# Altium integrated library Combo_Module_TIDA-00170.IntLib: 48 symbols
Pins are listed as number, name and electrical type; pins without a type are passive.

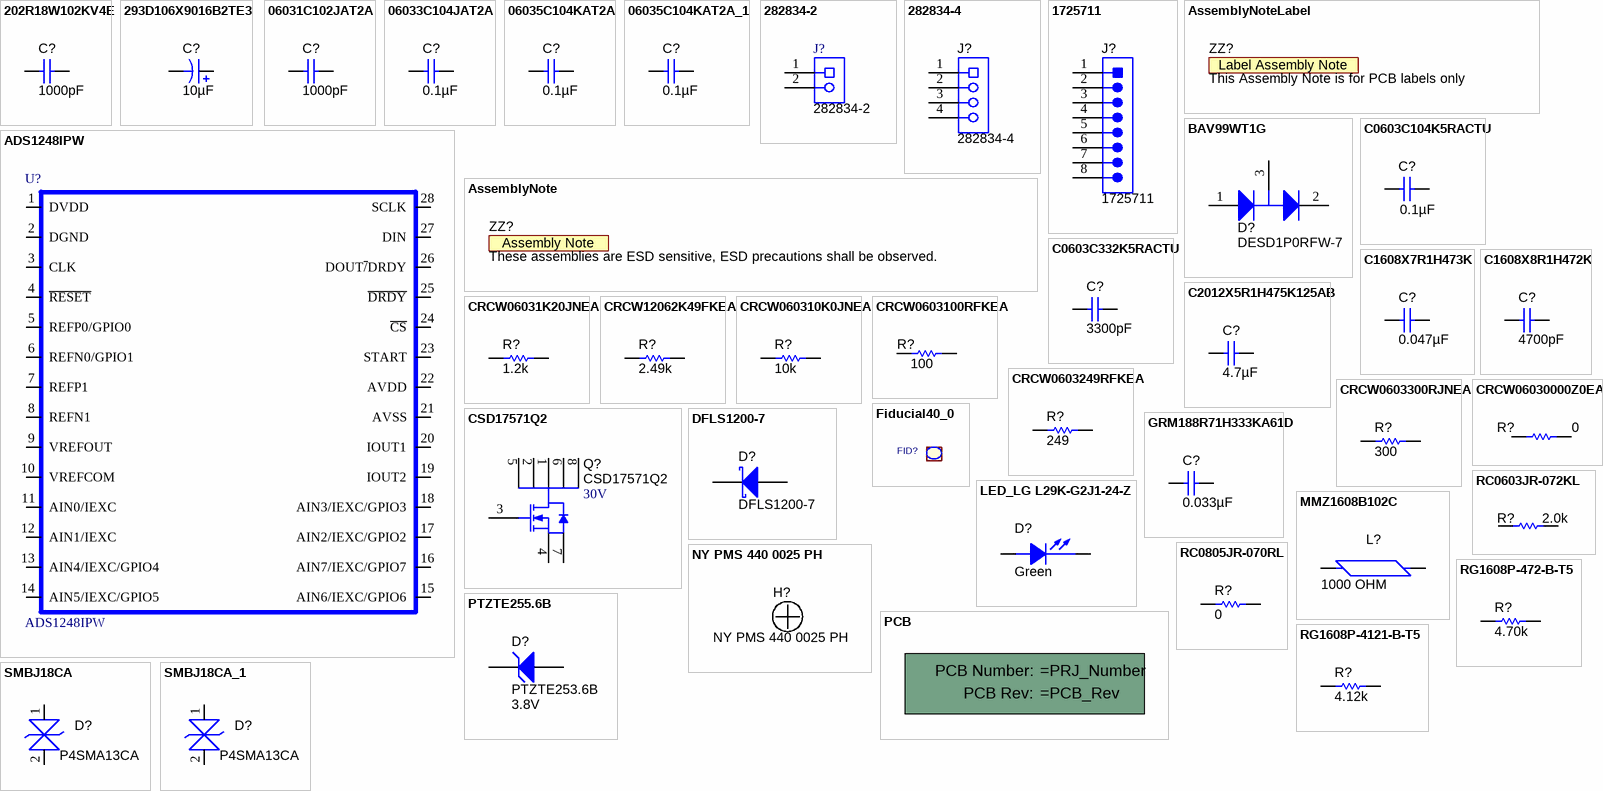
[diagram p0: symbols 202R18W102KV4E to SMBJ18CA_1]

## 202R18W102KV4E
designator C?, comment value 1000pF  (hidden comment: CC1206KRX7R0BB102)
CAP CER 1000PF 100V 10% X7R 1206; Manufacturer: Yageo; Polarized: N; CompType: Capacitor; Cap_F: 0.000000001; Tolerance_%: 0; Value2: 2KV; Cap_Case: 1206
signal-integrity model Cap
simulation model Cap
footprint 1206
footprint 1206M
footprint 1206L
pins: 1, 2

## 293D106X9016B2TE3
designator C?  ValueDisplayed: 10µF  (hidden comment: 293D106X9016B2TE3)
CAP, TA, 10 µF, 16 V, +/- 10%, 2 ohm, SMD; Manufacturer: Vishay-Sprague; Polarized: Y; CompType: Capacitor; Value: 10uF; U/M: EA; Cap_F: 0.00001; Tolerance_%: 10; Value1: 2 ohm; VDC_V: 16; Value2: 16V; ESR_ohm: 2; IRMS_A: 0.21; TaMin_C: -55; TaMax_C: 125; Cap_Case: B
signal-integrity model Cap
simulation model Cap
footprint 3528-21
pins: 1 +, 2 -

## 06031C102JAT2A
designator C?  ValueDisplayed: 1000pF  (hidden comment: 06031C102JAT2A)
CAP, CERM, 1000pF, 100V, +/-5%, X7R, 0603; Manufacturer: AVX; Polarized: N; CompType: Capacitor; U/M: EA; Cap_F: 0.000000001; Tolerance_%: 5; ESR_Ohm: 0.276; Value1: 0.276 ohm; VDC_V: 100; TaMin_C: -55; TaMax_C: 125; Cap_Case: 0603
signal-integrity model Cap
simulation model Cap
footprint 0603 (0603 from SM-752 data)
footprint 0603M
footprint 0603L
footprint 0603_HV
pins: 1, 2

## 06033C104JAT2A
designator C?  ValueDisplayed: 0.1µF  (hidden comment: 06033C104JAT2A)
CAP, CERM, 0.1uF, 25V, +/-5%, X7R, 0603; Manufacturer: AVX; Polarized: N; CompType: Capacitor; U/M: EA; Cap_F: 0.0000001; Tolerance_%: 5; ESR_Ohm: 0.05; Value1: 0.05 ohm; VDC_V: 25; TaMin_C: -55; TaMax_C: 125; Cap_Case: 0603
signal-integrity model Cap
simulation model Cap
footprint 0603 (0603 from SM-752 data)
footprint 0603M
footprint 0603L
footprint 0603_HV
pins: 1, 2

## 06035C104KAT2A
designator C?  ValueDisplayed: 0.1µF  (hidden comment: 06035C104KAT2A)
CAP, CERM, 0.1uF, 50V, +/-10%, X7R, 0603; Manufacturer: AVX; Polarized: N; CompType: Capacitor; U/M: EA; Cap_F: 0.0000001; Tolerance_%: 10; Value1: Unknown; VDC_V: 50; TaMin_C: -55; TaMax_C: 125; Cap_Case: 0603
signal-integrity model Cap
simulation model Cap
footprint 0603
footprint 0603M
footprint 0603L
footprint 0603_HV
footprint 0603S
pins: 1, 2

## 06035C104KAT2A_1
designator C?, comment ValueDisplayed: 0.1µF  (hidden comment: 06035C104KAT2A)
CAP, CERM, 0.1uF, 50V, +/-10%, X7R, 0603; Manufacturer: AVX; Polarized: N; CompType: Capacitor; U/M: EA; Cap_F: 0.0000001; Tolerance_%: 10; Value1: Unknown; VDC_V: 50; TaMin_C: -55; TaMax_C: 125; Cap_Case: 0603
signal-integrity model Cap
simulation model Cap
footprint 0603
footprint 0603M
footprint 0603L
footprint 0603_HV
pins: 1, 2

## 282834-2
designator J?
Terminal Block, 2x1, 2.54mm, TH; Manufacturer: TE Connectivity; SymbolCreator: a0412235; U/M: EA
footprint TEC_282834-2
pins: 1, 2

## 282834-4
designator J?
Receptacle, 100mil, 4X1 TH; Manufacturer: TE Connectivity; SymbolCreator: a0411947; U/M: EA
footprint TEC_282834-4
pins: 1, 2, 3, 4

## 1725711
designator J?
Terminal Block, 8x1, 2.54 mm, TH; Manufacturer: Phoenix Contact; SymbolCreator: a0411947; U/M: EA
footprint CONN_1725711
pins: 1, 2, 3, 4, 5, 6, 7, 8

## ADS1248IPW
designator U?
IC, 24-Bit A-D Converters for Temperature Sensors; Manufacturer: TI; Alternate Manufacturer: None; Area: 164.280
footprint PW28
pins: 1 DVDD, 2 DGND, 3 CLK, 4 ~{RESET}, 5 REFP0/GPIO0, 6 REFN0/GPIO1, 7 REFP1, 8 REFN1, 9 VREFOUT, 10 VREFCOM, 11 AIN0/IEXC, 12 AIN1/IEXC, 13 AIN4/IEXC/GPIO4, 14 AIN5/IEXC/GPIO5, 15 AIN6/IEXC/GPIO6, 16 AIN7/IEXC/GPIO7, 17 AIN2/IEXC/GPIO2, 18 AIN3/IEXC/GPIO3, 19 IOUT2, 20 IOUT1, 21 AVSS, 22 AVDD, 23 START, 24 ~{CS}, 25 ~{DRDY}, 26 DOUT~{/}DRDY, 27 DIN, 28 SCLK

## AssemblyNote
designator ZZ?, comment These assemblies are ESD sensitive, ESD precautions shall be observed.  (no BOM)
SymbolCreator: codlsc; CompType: AssemblyNote
footprint AssemblyNote

## AssemblyNoteLabel
designator ZZ?, comment This Assembly Note is for PCB labels only  (no BOM)
SymbolCreator: a0412235
footprint AssemblyNoteLabel

## BAV99WT1G
designator D?, comment DESD1P0RFW-7
Diode, P-N, 70V, 0.2A, SOT-323; Manufacturer: Diodes Inc; Value: DNP
footprint SOT-323
pins: 1 A, 2 K, 3 C
1 alternate drawing of the same symbol

## C0603C104K5RACTU
designator C?  ValueDisplayed: 0.1µF  (hidden comment: C0603C104K5RACTU)
CAP, CERM, 0.1uF, 50V, +/-10%, X7R, 0603; Manufacturer: Kemet; Polarized: N; CompType: Capacitor; U/M: EA; Cap_F: 0.0000001; Tolerance_%: 10; Value1: Unknown; VDC_V: 50; TaMin_C: -55; TaMax_C: 125; Cap_Case: 0603
signal-integrity model Cap
simulation model Cap
footprint 0603
footprint 0603M
footprint 0603L
footprint 0603_HV
footprint 0603S
pins: 1, 2

## C0603C332K5RACTU
designator C?  ValueDisplayed: 3300pF  (hidden comment: C0603C332K5RACTU)
CAP, CERM, 3300pF, 50V, +/-10%, X7R, 0603; Manufacturer: Kemet; Polarized: N; CompType: Capacitor; U/M: EA; Cap_F: 0.0000000033; Tolerance_%: 10; Value1: Unknown; VDC_V: 50; TaMin_C: -55; TaMax_C: 125; Cap_Case: 0603
signal-integrity model Cap
simulation model Cap
footprint 0603
footprint 0603M
footprint 0603L
footprint 0603_HV
footprint 0603S
pins: 1, 2

## C1608X7R1H473K
designator C?  ValueDisplayed: 0.047µF  (hidden comment: C1608X7R1H473K)
CAP, CERM, 0.047uF, 50V, +/-10%, X7R, 0603; Manufacturer: TDK; Polarized: N; CompType: Capacitor; U/M: EA; Cap_F: 0.000000047; Tolerance_%: 10; ESR_Ohm: 0.0234; Value1: 0.0234 ohm; VDC_V: 50; TaMin_C: -55; TaMax_C: 125; Cap_Case: 0603
signal-integrity model Cap
simulation model Cap
footprint 0603
footprint 0603M
footprint 0603L
footprint 0603_HV
footprint 0603S
pins: 1, 2

## C1608X8R1H472K
designator C?  ValueDisplayed: 4700pF  (hidden comment: C1608X8R1H472K)
CAP, CERM, 4700pF, 50V, +/-10%, X8R, 0603; Manufacturer: TDK; Polarized: N; CompType: Capacitor; U/M: EA; Cap_F: 0.0000000047; Tolerance_%: 10; ESR_Ohm: 0.0973; Value1: 0.0973 ohm; VDC_V: 50; TaMin_C: -55; TaMax_C: 150; Cap_Case: 0603
signal-integrity model Cap
simulation model Cap
footprint 0603
footprint 0603M
footprint 0603L
footprint 0603_HV
footprint 0603S
pins: 1, 2

## C2012X5R1H475K125AB
designator C?  ValueDisplayed: 4.7µF  (hidden comment: C2012X5R1H475K125AB)
CAP, CERM, 4.7uF, 50V, +/-10%, X5R, 0805; Manufacturer: TDK; Polarized: N; CompType: Capacitor; U/M: EA; Cap_F: 0.0000047; Tolerance_%: 10; Value1: Unknown; VDC_V: 50; TaMin_C: -55; TaMax_C: 85; Cap_Case: 0805
signal-integrity model Cap
simulation model Cap
footprint 0805_HV
footprint 0805
footprint 0805M
footprint 0805L
pins: 1, 2

## CRCW06031K20JNEA
designator R?  ValueDisplayed: 1.2k  (hidden comment: CRCW06031K20JNEA)
RES, 1.2 k, 5%, 0.1 W, 0603; Manufacturer: Vishay-Dale; CompType: Resistor; Res_ohm: 1200; Value: 1.2k; Value_Code: 1k20; Tolerance_%: 5; Power_W: 0.1; Value2: 0.1W; VDC_V: 75; TempCo: 200 ppm/C; EIA_Code: E24; U/M: EA
signal-integrity model Resistor
simulation model Resistor
footprint 0603
footprint 0603M
footprint 0603L
footprint 0603_HV
footprint 0603S
pins: 1, 2

## CRCW12062K49FKEA
designator R?, comment value 2.49k  (hidden comment: TNPW12062K49BEEA)
RES 2.49K OHM 1/4W 0.1% 1206; Manufacturer: Vishay-Dale; CompType: Resistor; Res_ohm: 2490; Value_Code: 2k49; Tolerance_%: 1; Power_W: 0.25; Value2: 0.25W; VDC_V: 200; TempCo: 100 ppm/C; EIA_Code: E96; U/M: EA
signal-integrity model Resistor
simulation model Resistor
footprint 1206
footprint 1206M
footprint 1206L
pins: 1, 2

## CRCW060310K0JNEA
designator R?  ValueDisplayed: 10k  (hidden comment: CRCW060310K0JNEA)
RES, 10 k, 5%, 0.1 W, 0603; Manufacturer: Vishay-Dale; CompType: Resistor; Res_ohm: 10000; Value: 10k; Value_Code: 10k0; Tolerance_%: 5; Power_W: 0.1; Value2: 0.1W; VDC_V: 75; TempCo: 200 ppm/C; EIA_Code: E24; U/M: EA
signal-integrity model Resistor
simulation model Resistor
footprint 0603
footprint 0603M
footprint 0603L
footprint 0603_HV
footprint 0603S
pins: 1, 2

## CRCW0603100RFKEA
designator R?  ValueDisplayed: 100  (hidden comment: CRCW0603100RFKEA)
RES, 100, 1%, 0.1 W, 0603; Manufacturer: Vishay-Dale; CompType: Resistor; Value: 100; Value_Code: 100R; Tolerance_%: 1; Power_W: 0.1; Value2: 0.1W; VDC_V: 75; TempCo: 100 ppm/C; EIA_Code: E96; U/M: EA
signal-integrity model Resistor
simulation model Resistor
footprint 0603
footprint 0603M
footprint 0603L
footprint 0603_HV
footprint 0603S
pins: 1, 2

## CRCW0603249RFKEA
designator R?  ValueDisplayed: 249  (hidden comment: CRCW0603249RFKEA)
RES, 249, 1%, 0.1 W, 0603; Manufacturer: Vishay-Dale; CompType: Resistor; Value: 249; Value_Code: 249R; Tolerance_%: 1; Power_W: 0.1; Value2: 0.1W; VDC_V: 75; TempCo: 100 ppm/C; EIA_Code: E96; U/M: EA
signal-integrity model Resistor
simulation model Resistor
footprint 0603
footprint 0603M
footprint 0603L
footprint 0603_HV
footprint 0603S
pins: 1, 2

## CRCW0603300RJNEA
designator R?  value 300  (hidden comment: CRCW0603300RJNEA)
RES, 300 ohm, 5%, 0.1W, 0603; Manufacturer: Vishay-Dale; CompType: Resistor; Value_Code: 300R; Tolerance_%: 5; Power_W: 0.1; VDC_V: 75; TempCo: 200 ppm/C; EIA_Code: E24; U/M: EA
signal-integrity model Resistor
simulation model Resistor
footprint 0603 (0603 from SM-752 data)
footprint 0603M
footprint 0603L
footprint 0603_HV
footprint 0603
footprint 0603_HV
footprint 0603L
footprint 0603M
simulation model Resistor
signal-integrity model Resistor
pins: 1, 2

## CRCW06030000Z0EA
designator R?  ValueDisplayed: 0  (hidden comment: CRCW06030000Z0EA)
RES, 0, 5%, 0.1 W, 0603; Manufacturer: Vishay-Dale; CompType: Resistor; Value: 0; Value_Code: 0000; Tolerance_%: 5; Power_W: 0.1; Value2: 0.1W; VDC_V: 75; TempCo: 200 ppm/C; EIA_Code: E24; U/M: EA
signal-integrity model Resistor
simulation model Resistor
footprint 0603
footprint 0603M
footprint 0603L
footprint 0603_HV
footprint 0603S
pins: 1, 2

## CSD17571Q2
designator Q?  value 30V
MOSFET, N-CH, 30V, 22A, SON 2X2 MM; Manufacturer: TEXAS INSTRUMENTS; CompType: POWER MOSFET
footprint SON_CSD17571Q2 (Footprint not found)
pins: 1 D, 2 D, 3 G, 4 S, 5 D, 6 D, 7 S, 8 D

## DFLS1200-7
designator D?
Diode, Schottky, 200V, 1A, PowerDI123; Manufacturer: Diodes Inc.; U/M: EA; Vf_V: 0.85; Value2: 0.85V; Io_A: 1; Vr_V: 200; TJmax_C: 175; RJC_CperW: 7
signal-integrity model Diode
simulation model DI_DFLS1200
footprint powerDI123
pins: 1 K, 2 A

## Fiducial40_0
designator FID?, comment Fiducial40_80  (value not drawn)
footprint FID_TOP_40_80
footprint FID_TOP_40_80
footprint FID_TOP_40_80BA
pins: 1

## GRM188R71H333KA61D
designator C?  ValueDisplayed: 0.033µF  (hidden comment: GRM188R71H333KA61D)
CAP, CERM, 0.033uF, 50V, +/-10%, X7R, 0603; Manufacturer: MuRata; Polarized: N; CompType: Capacitor; U/M: EA; Cap_F: 0.000000033; Tolerance_%: 10; Value1: Unknown; VDC_V: 50; TaMin_C: -55; TaMax_C: 125; Cap_Case: 0603
signal-integrity model Cap
simulation model Cap
footprint 0603
footprint 0603M
footprint 0603L
footprint 0603_HV
footprint 0603S
pins: 1, 2

## LED_LG L29K-G2J1-24-Z
designator D?  value Green  (hidden comment: LED_LG L29K-G2J1-24-Z)
LED SmartLED Green 570NM; Manufacturer: OSRAM; SymbolCreator: x0120606
footprint LED0603AA
pins: 1 C, 2 A

## MMZ1608B102C
designator L?, comment 1000 OHM
FERRITE CHIP 1000 OHM 300MA 0603; PartNumber: MMZ1608B102C; Manufacturer: TDK Corporation; CompType: Ferrite Bead
footprint FB0603
pins: 1, 2

## NY PMS 440 0025 PH
designator H?
Machine Screw, Round, #4-40 x 1/4, Nylon, Philips panhead; Manufacturer: B&F Fastener Supply; CompType: Hardware; SymbolCreator: codlsc; U/M: EA
footprint NY PMS 440 0025 PH

## PCB
designator !PCB?, comment Printed Circuit Board  (value not drawn)  (mechanical)
Manufacturer: Any; SymbolCreator: a0412235; CompType: PCB
1 alternate drawing of the same symbol

## PTZTE255.6B
designator D?, comment PTZTE253.6B  value 3.8V
DIODE ZENER 3.8V 1W PMDS; Manufacturer: Rohm Semiconductor; U/M: EA; Vz_V: 3.8
signal-integrity model Diode
footprint powerDI123
pins: 1 K, 2 A

## RC0603JR-072KL
designator R?  ValueDisplayed: 2.0k  (hidden comment: RC0603JR-072KL)
RES, 2.0 k, 5%, 0.1 W, 0603; Manufacturer: Yageo America; CompType: Resistor; Res_ohm: 2000; Value: 2.0k; Value_Code: 2k00; Tolerance_%: 5; Power_W: 0.1; Value2: 0.1W; VDC_V: 50; TempCo: 100 ppm/C; EIA_Code: E24; U/M: EA
signal-integrity model Resistor
simulation model Resistor
footprint 0603
footprint 0603M
footprint 0603L
footprint 0603_HV
footprint 0603S
pins: 1, 2

## RC0805JR-070RL
designator R?  value 0  (hidden comment: RC0805JR-070RL)
RES, 0 ohm, 5%, 0.125W, 0805; Manufacturer: Yageo America; CompType: Resistor; Value_Code: 0000; Tolerance_%: 5; Power_W: 0.125; VDC_V: 150; TempCo: 200 ppm/C; EIA_Code: E24; U/M: EA
signal-integrity model Resistor
simulation model Resistor
footprint 0805_HV
footprint 0805
footprint 0805M
footprint 0805L
pins: 1, 2

## RG1608P-472-B-T5
designator R?  value 4.70k  (hidden comment: RG1608P-472-B-T5)
RES, 4.70k ohm, 0.1%, 0.1W, 0603; Manufacturer: Susumu Co Ltd; CompType: Resistor; Res_ohm: 4700; Value_Code: 4k70; Tolerance_%: 0.1; VDC_V: 75; TempCo: 25 ppm/C; EIA_Code: E192; U/M: EA
signal-integrity model Resistor
simulation model Resistor
footprint 0603
footprint 0603M
footprint 0603L
footprint 0603_HV
footprint 0603S
pins: 1, 2

## RG1608P-4121-B-T5
designator R?  value 4.12k  (hidden comment: RG1608P-4121-B-T5)
RES, 4.12k ohm, 0.1%, 0.1W, 0603; Manufacturer: Susumu Co Ltd; CompType: Resistor; Res_ohm: 4120; Value_Code: 4k12; Tolerance_%: 0.1; VDC_V: 75; TempCo: 25 ppm/C; EIA_Code: E192; U/M: EA
signal-integrity model Resistor
simulation model Resistor
footprint 0603
footprint 0603M
footprint 0603L
footprint 0603_HV
footprint 0603S
pins: 1, 2

## SMBJ18CA
designator D?, comment P4SMA13CA
TVS DIODE 11.1VWM 18.2VC SMD; Manufacturer: Littelfuse Inc
footprint DIO_DO214AC_SMA_BI (DIODE, BIDIRECTIONAL, DO-214AC, 2-PIN)
footprint DIO_DO214AC_SMA_BI (DIODE, BIDIRECTIONAL, DO-214AC, 2-PIN)
pins: 1, 2

## SMBJ18CA_1
designator D?, comment P4SMA13CA
TVS DIODE 11.1VWM 18.2VC SMD; Manufacturer: Littelfuse Inc
footprint DIO_DO214AC_SMA_BI (DIODE, BIDIRECTIONAL, DO-214AC, 2-PIN)
pins: 1, 2

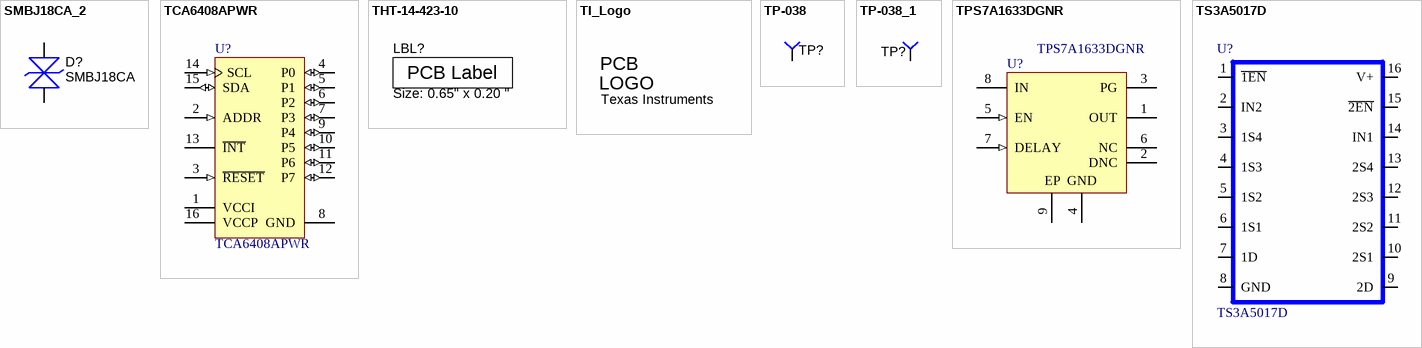
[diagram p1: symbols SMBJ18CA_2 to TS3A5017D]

## SMBJ18CA_2
designator D?, comment SMBJ18CA
TVS 18 VOLT 600 WATT BI-DIR SMB; Manufacturer: Littelfuse Inc
footprint DIO_SMB_BIAAAA
pins: 1, 2

## TCA6408APWR
designator U?
Low-Voltage 8-Bit I2C and SMBus I/O Expander, 1.65 to 5.5 V, -40 to 85 degC, 16-pin TSSOP (PW), Green (RoHS & no Sb/Br); Manufacturer: Texas Instruments; Alternate Manufacturer: None; Alternate PartNumber: Equivalent; SubFamily: I2C IO Expander; No. of Outputs: 8; Interrupt Output: Yes; fSCLK(Max)(MHz): 400; VCC(Min)(V): 1.65; VCC(Max)(V): 5.5; I2C Address: 0100 00x
footprint PW0016A_N (TSOP, 16-Leads, Body 5x4.4mm, Pitch 0.65mm, IPC Medium Density)
footprint PW0016A_L (TSOP, 16-Leads, Body 5x4.4mm, Pitch 0.65mm, IPC High Density)
footprint PW0016A_M (TSOP, 16-Leads, Body 5x4.4mm, Pitch 0.65mm, IPC Low Density)
pins: 1 VCCI (power) "Supply voltage of I2C bus. Connect directly to the VCCI of the external I2C master. Provides voltage leveltranslation", 2 ADDR (in) "Address input. Connect directly to VCCI or ground", 3 ~{RESET} (in) "Active-low reset input. Connect to VCC  through a pullup resistor, if no active connection is used.", 4 P0 (io) "P-port input/output. (Push-pull design structure.) At power on, P0 is configured as an input.", 5 P1 (io) "P-port input/output. (Push-pull design structure.) At power on, P1 is configured as an input.", 6 P2 (io) "P-port input/output. (Push-pull design structure.) At power on, P2 is configured as an input.", 7 P3 (io) "P-port input/output. (Push-pull design structure.) At power on, P3 is configured as an input.", 8 GND (power) "Ground", 9 P4 (io) "P-port input/output. (Push-pull design structure.) At power on, P4 is configured as an input.", 10 P5 (io) "P-port input/output. (Push-pull design structure.) At power on, P5 is configured as an input.", 11 P6 (io) "P-port input/output. (Push-pull design structure.) At power on, P6 is configured as an input.", 12 P7 (io) "P-port input/output. (Push-pull design structure.) At power on, P7 is configured as an input.", 13 ~{INT} (oc) "Interrupt output. Connect to VCCI through a pullup resistor.", 14 SCL (in) "Serial clock bus. Connect to VCCI through a pullup resistor.", 15 SDA (io) "Serial data bus. Connect to VCCI through a pullup resistor.", 16 VCCP (power) "Supply voltage of TCA6408A for P port"

## THT-14-423-10
designator LBL?, comment Size: 0.65" x 0.20 "
Thermal Transfer Printable Labels, 0.650" W x 0.200" H - 10,000 per roll; Manufacturer: Brady; PartNumber: THT-14-423-10; SymbolCreator: a0412235; CompType: Label
footprint Label_650x200

## TI_Logo
designator Logo?, comment Texas Instruments  (no BOM)
Texas Instrument Corporate Signature; SymbolCreator: codlsc
footprint TI_Stacked_SolderMask_Medium
footprint TI_Stacked_SolderMask_Small
footprint TI_Stacked_Overlay_Medium
footprint TI_Stacked_Overlay_Small
footprint TI_Horizontal_SolderMask_Medium
footprint TI_Horizontal_SolderMask_Small
footprint TI_Horizontal_Overlay_Medium
footprint TI_Horizontal_Overlay_Small
footprint TI_Symbol_SolderMask_Small
footprint TI_Symbol_Overlay_Medium
footprint TI_Symbol_Overlay_Small
footprint TI_Symbol_SolderMask_Medium

## TP-038
designator TP?  (value not drawn)
Test Point 40mil pad 20mil drill; Manufacturer: STD; Value: STD
footprint TP-038
footprint TP1_PD40_D0.5_S50
footprint TP1_PD40_D0.5_S50
pins: 1

## TP-038_1
designator TP?, comment TP-038  (value not drawn)
Test Point 40mil pad 20mil drill; Manufacturer: STD; Value: STD
footprint TP-038
footprint TP1_PD40_D0.5_S50
pins: 1

## TPS7A1633DGNR
designator U?
Single Output LDO, 100 mA, Fixed 3.3 V Output, 3 to 60 V Input, with Enable and Power Good, 8-pin MSOP (DGN), -40 to 125 degC, Green (RoHS & no Sb/Br); Manufacturer: Texas Instruments; Alternate Manufacturer: None; Alternate PartNumber: Equivalent; Accuracy(%): 2; Fixed Output Options(V): 3.3; Iout(Max)(A): 0.1; Iq(Typ)(mA): 0.004; Power Good: TRUE; Rating: Catalog; SubFamily: Single Channel LDO; Vdo(Typ)(mV): 60; Vin(Min)(V): 3
footprint DGN0008C_N (SOIC, 8-Leads, Body 3x3mm, Pitch 0.65mm, Thermal Pad 1.79X1.47mm, IPC Medium Density)
footprint DGN0008C_L (SOIC, 8-Leads, Body 3x3mm, Pitch 0.65mm, Thermal Pad 1.79X1.47mm, IPC High Density)
footprint DGN0008C_M (SOIC, 8-Leads, Body 3x3mm, Pitch 0.65mm, Thermal Pad 1.79X1.47mm, IPC Low Density)
pins: 1 OUT (power) "Regulator output pin. A capacitor > 2.2 uF must be tied from this pin to ground to assure stability. It is recommended to connect a 10 uF ceramic capacitor from OUT to GND (as close to the device as possible) to maximize AC (See Datasheet)", 2 DNC "For the fixed voltage versions: DO NOT CONNECT to this pin. Do not route this pin to any electrical net, not even GND or IN.", 3 PG (hiz) "Power-good pin. Open collector output; leave open or connect to GND if the power-good function is not needed.", 4 GND (power) "Ground pin.", 5 EN (in) "Enable pin. This pin turns the regulator on or off.If VEN >= VEN_HI, the regulator is enabled. If VEN =< VEN_LO, the regulator is disabled. If not used, the EN pin can be connected to IN. Make sure that VEN =< VIN at all (See Datasheet)", 6 NC "This pin can be left open or tied to any voltage between GND and IN.", 7 DELAY (in) "Delay pin. Connect a capacitor to GND to adjust the PG delay time; leave open if the reset function is not needed.", 8 IN (power) "Regulator input supply pin. A capacitor > 0.1 uF must be tied from this pin to ground to assure stability. It is recommended to connect a 10 uF ceramic capacitor from IN to GND (as close to the device as possible) to reduce (See Datasheet)", 9 EP (power) "Solder to printed circuit board (PCB) to enhance thermal performance. Although it can be left floating, it is highly recommended to connect the PowerPAD to the GND plane."

## TS3A5017D
designator U?
IC, Dual, 14 Ohms SP4T Analog Switch; Manufacturer: TI; Alternate Manufacturer: None; AREA: 145200
footprint SO16
pins: 1 ~{1EN}, 2 IN2, 3 1S4, 4 1S3, 5 1S2, 6 1S1, 7 1D, 8 GND, 9 2D, 10 2S1, 11 2S2, 12 2S3, 13 2S4, 14 IN1, 15 ~{2EN}, 16 V+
